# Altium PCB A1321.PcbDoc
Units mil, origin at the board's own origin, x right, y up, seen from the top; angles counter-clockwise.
Board outline 2175 x 1000 mil, 2 copper layers (Top Layer, Bottom Layer); 35 components, 22 nets, 125 pads, 412 vias.
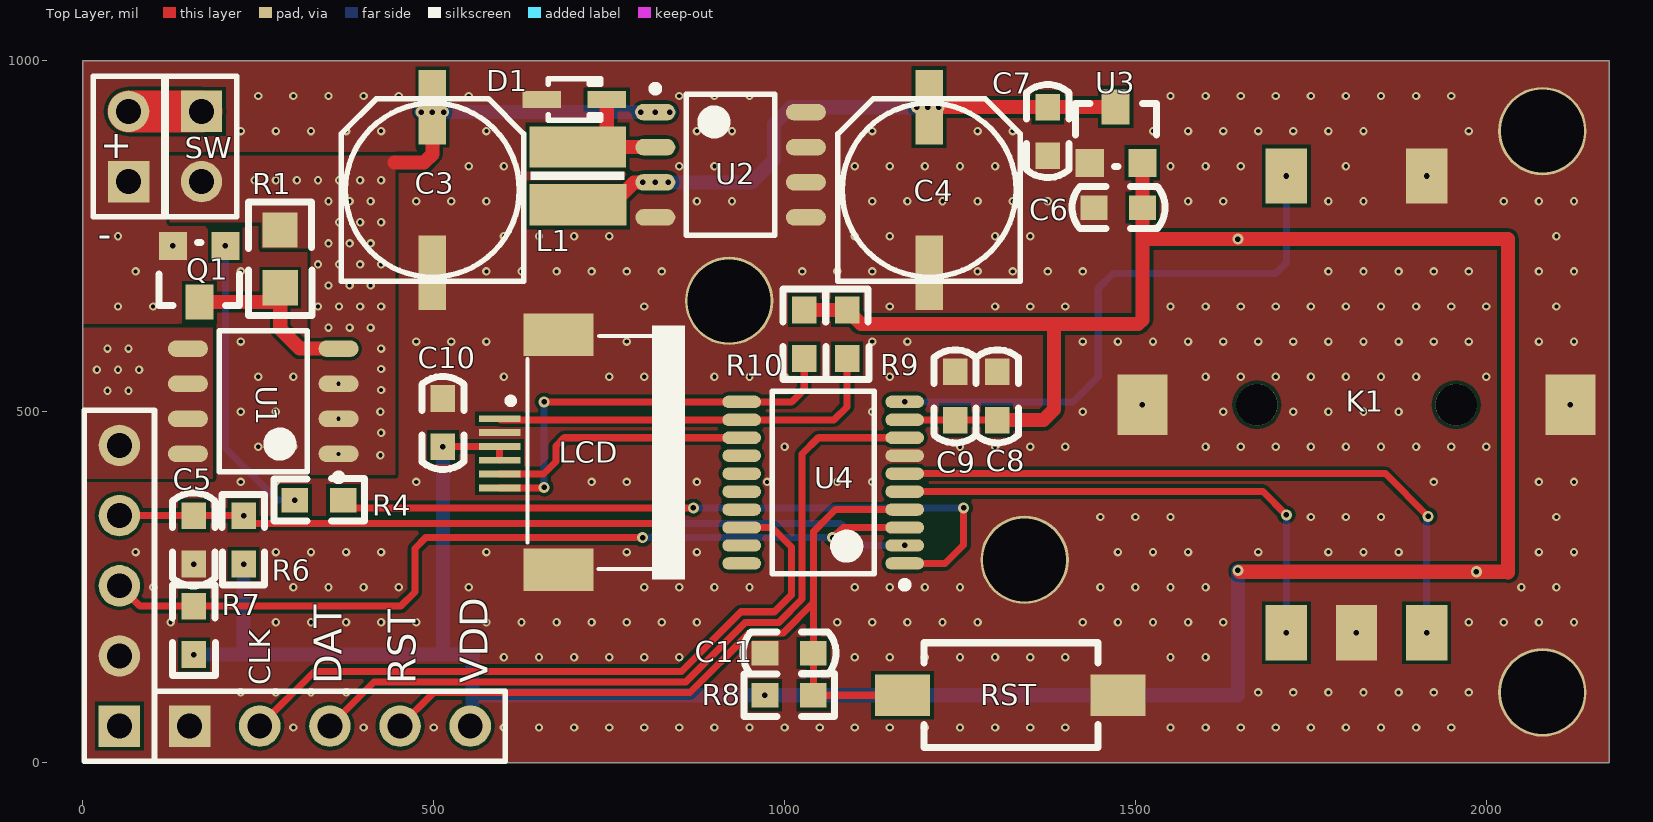
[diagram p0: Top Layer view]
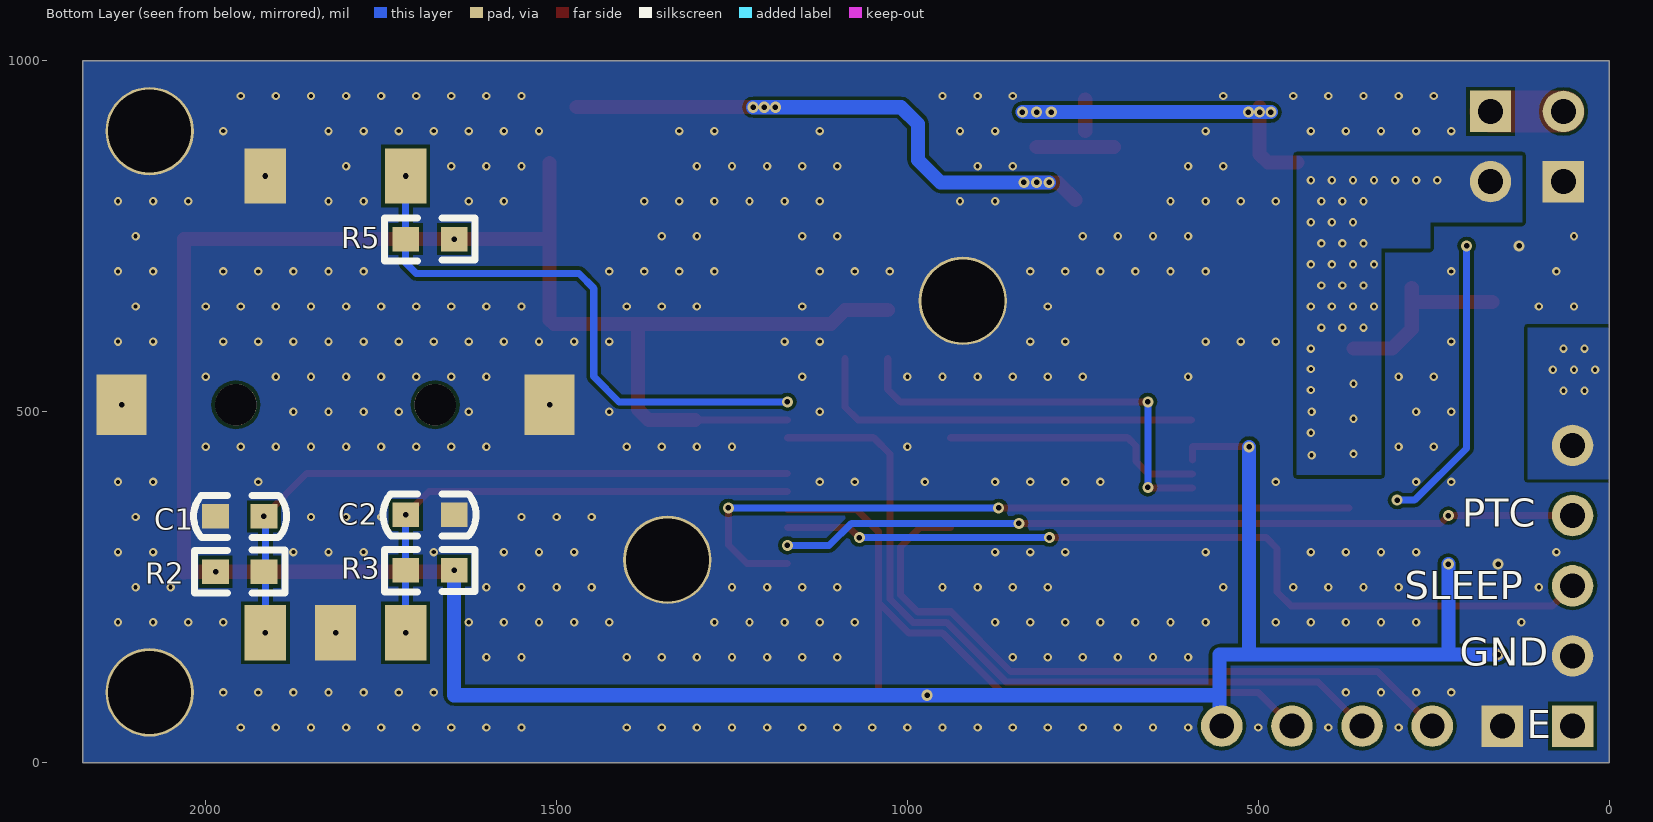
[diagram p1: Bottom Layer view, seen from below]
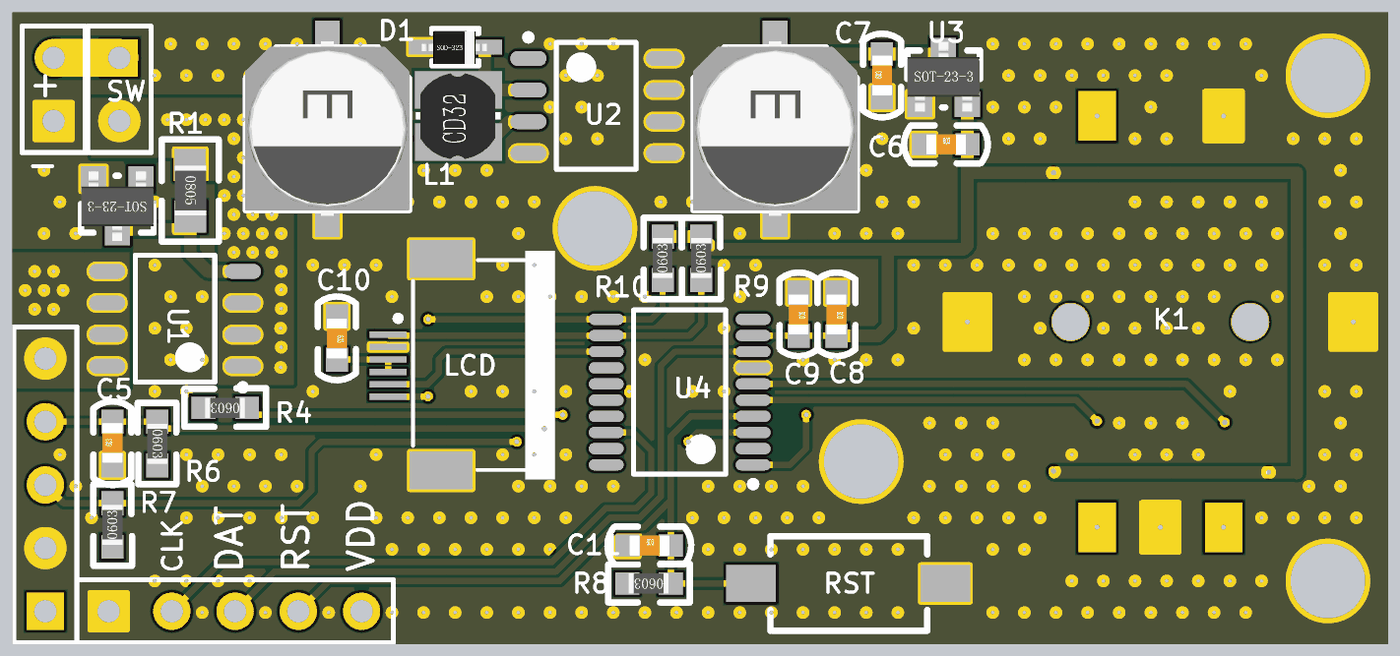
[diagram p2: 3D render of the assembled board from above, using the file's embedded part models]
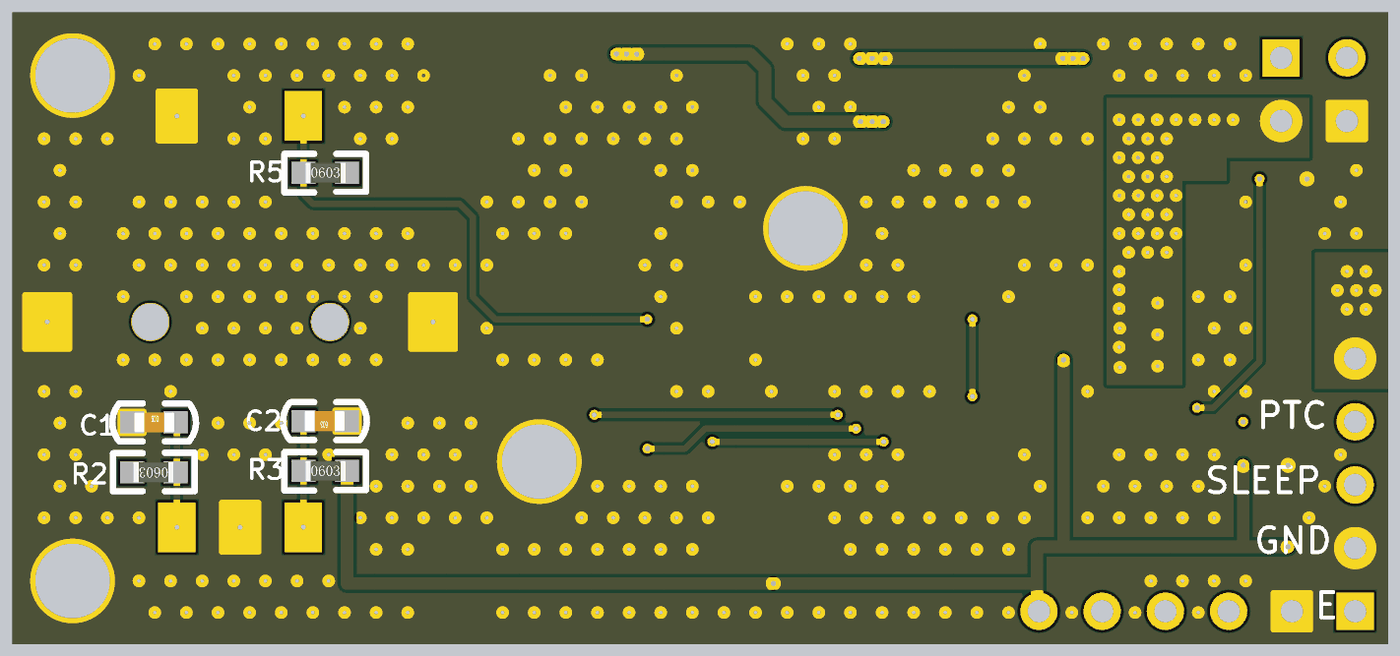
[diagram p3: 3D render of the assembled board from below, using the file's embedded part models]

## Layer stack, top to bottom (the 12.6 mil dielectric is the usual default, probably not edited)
Top Solder: solder mask 0.4, Solder Resist, Dk 3.5
Top Layer: signal copper 1.4
Dielectric 1: dielectric 12.6, FR-4, Dk 4.8
Bottom Layer: signal copper 1.4
Bottom Solder: solder mask 0.4, Solder Resist, Dk 3.5

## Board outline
0,0 0,1000 2175,1000 2175,0

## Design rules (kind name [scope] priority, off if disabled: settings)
Clearance [All] p1: gap=5
PolygonConnect [All] p1: connectstyle=Direct reliefconductorwidth=10 reliefentries=4 polygonreliefangle="90 Angle" airgapwidth=10
RoutingVias [All] p1: holewidth=8 width=14 viastyle="Through Hole" minholewidth=8 minwidth=14 maxholewidth=28 maxwidth=50
SolderMaskExpansion [All] p1: expansion=4
Width [All] p1: maxlimit=100 minlimit=5 preferedwidth=5
30 further rules are at their usual default settings.

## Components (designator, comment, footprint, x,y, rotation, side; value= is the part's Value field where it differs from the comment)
C1 "C0603" C0603 1986,351 r180 bottom
C2 "C0603" C0603 1646,353 r0 bottom
C3 "Capacitor" C6.3*6.3 498,816 r270 top
C4 "Capacitor" C6.3*6.3 1206,816 r270 top
C5 "C0603" C0603 158,283 r90 top
C6 "C0603" C0603 1441,791 r0 top
C7 "C0603" C0603 1375,865 r90 top
C8 "C0603" C0603 1303,557 r270 top
C9 "C0603" C0603 1243,557 r270 top
C10 "C0603" C0603 513,519 r270 top
C11 "C0603" C0603 972,156 r0 top
CLK "" HDR1X5 152,52 r0 top (schematic designator P4)
D1 "1N5819" SOD323 654,945 r0 top
K1 "EC12" EC12 1815,510 r0 top
L1 "CD32" CD32 705,836 r90 top
LCD "FPC6PIN-0.5" FPC6PIN-0.5 594,490 r270 top (schematic designator LCD1)
P2 "" HDR1X2 65,828 r90 top
P3 "" HDR1X5 52,52 r90 top
Q1 "S8050" SOT23 166,702 r180 top
R1 "R0805" R0805 281,759 r270 top
R2 "R0603" R0603 1917,272 r0 bottom
R3 "R0603" R0603 1715,274 r180 bottom
R4 "R0603" R0603 371,374 r180 top
R5 "R0603" R0603 1715,746 r180 bottom
R6 "R0603" R0603 229,352 r270 top
R7 "R0603" R0603 158,154 r90 top
R8 "R0603" R0603 1041,96 r180 top
R9 "R0603" R0603 1089,576 r90 top
R10 "R0603" R0603 1028,576 r90 top
RST "KEY" KEY_SMD 1475,96 r180 top (schematic designator KEY1)
SW "" HDR1X2 169,928 r270 top (schematic designator P1)
U1 "AO4407" SOP8 257,515 r180 top
U2 "XL1509" SOP8 923,852 r0 top
U3 "XC6206P332MR" SOT23 1472,889 r0 top
U4 "N76E003AT20" N76E003AT20 1055,399 r180 top

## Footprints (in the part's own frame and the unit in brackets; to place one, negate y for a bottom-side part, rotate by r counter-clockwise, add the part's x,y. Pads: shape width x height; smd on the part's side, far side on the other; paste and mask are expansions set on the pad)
C6.3*6.3 [mm]
  rect 2.7x1 smd: 1(-3,0) 2(3,0)
  silkscreen extent -3.3,-3.3 3.3,3.3, body extent -3.5,-3.3 3.5,3.3, height 5.2
C0603 [mil]
  rect 38x35 smd: 1(0,0) 2(69,0)
  silkscreen extent -31,-30 101,30, body extent 4,-16 67,16, height 12
CD32 [mm]
  rect 1.5x3.5 smd mask+0: 1(-1.047,-0.012) 2(1.05,0)
  silkscreen extent -0.14,-1.69 0.16,1.71, body extent -1.74,-1.47 1.72,1.53, height 2
EC12 [mm]
  round 1.5 hole 1.5: 0(-3.607,0) 0(3.607,0)
  rect 1.5x2 all layers, no hole: 1(2.54,-8.255) 2(0,-8.255) 3(-2.54,-8.255) 4(-2.54,8.28) 5(2.54,8.28)
  rect 1.8x2.2 all layers, no hole: 6(-7.747,0) 7(7.747,0)
FPC6PIN-0.5 [mm]
  rect 0.25x1.5 smd: 1(0,0) 2(0.5,0) 3(1,0) 4(1.5,0) 5(2,0) 6(2.5,0)
  rect 1.524x2.54 smd: 7(5.466,2.13) 8(-3.043,2.13)
  silkscreen extent -3.37,0.3 5.82,6.7, body extent -3.35,-0.15 5.8,6.5, height 2.12
HDR1X2 [mm] "Connector; Header; 2 Position"
  rect 1.5x1.5 hole 0.9: 1(0,0)
  round 1.5 hole 0.9: 2(2.54,0)
  silkscreen extent -1.27,-1.27 3.81,1.27
HDR1X5 [mm] "Connector; Header; 5 Position"
  rect 1.5x1.5 hole 0.9: 1(0,0)
  round 1.5 hole 0.9: 2(2.54,0) 3(5.08,0) 4(7.62,0) 5(10.16,0)
  silkscreen extent -1.27,-1.27 11.43,1.27
KEY_SMD [mm]
  rect 2x1.5 smd: 1(0,0) 2(7.8,0)
  silkscreen extent 0.73,-1.9 7.03,1.9, body extent -0.06,-1.94 7.83,1.91, height 2.5
N76E003AT20 [mm]
  oval 1.4x0.45 smd: 1(-2.95,2.925) 2(-2.95,2.275) 3(-2.95,1.625) 4(-2.95,0.975) 5(-2.95,0.325) 6(-2.95,-0.325) 7(-2.95,-0.975) 8(-2.95,-1.625) 9(-2.95,-2.275) 10(-2.95,-2.925) 11(2.95,-2.925) 12(2.95,-2.275) 13(2.95,-1.625) 14(2.95,-0.975) 15(2.95,-0.325) 16(2.95,0.325) 17(2.95,0.975) 18(2.95,1.625) 19(2.95,2.275) 20(2.95,2.925)
  silkscreen extent -3.08,-3.3 1.85,3.82, body extent -2.25,-3.3 2.25,3.3, height 1.2
R0603 [mil]
  rect 38x35 smd: 1(0,0) 2(69,0)
  silkscreen extent -30,-31 99,30, body extent 4,-16 66,16, height 18
R0805 [mil]
  rect 50x50 smd: 1(0,0) 2(82.3,0.2)
  silkscreen extent -40,-45 122,45, body extent 1,-24 80,25, height 22
SOD323 [mm]
  rect 1.4x0.6 smd: 1(0,0) 2(2.35,0)
  silkscreen extent 0.22,-0.75 2.12,0.75, body extent -0.17,-0.67 2.43,0.63, height 1
SOP8 [mm] "SOP, 8-Leads, Body 4.90x3.90mm, Pitch 1.27mm, IPC Medium Density"
  oval 1.45x0.6 smd: 1(-2.725,1.905) 2(-2.725,0.635) 3(-2.725,-0.635) 4(-2.725,-1.905) 5(2.725,-1.905) 6(2.725,-0.635) 7(2.725,0.635) 8(2.725,1.905)
  silkscreen extent -2.85,-2.55 1.6,2.88, body extent -2,-2.55 2,2.55, height 1.75
SOT23 [mil]
  rect 40x40 smd: 1(-37.12,-34.37) 2(37.88,-34.37)
  rect 40x50 smd: 3(-0.12,45.63)
  silkscreen extent -57,-39 58,51, body extent -57,-46 57,64, height 47

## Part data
C3 C4: library part C6.3*6.3
CLK P3: library part "Header 5", "Header, 5-Pin"
D1: library part 1N5825
P2 SW: library part "Header 2", "Header, 2-Pin"

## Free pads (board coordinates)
  round 125.98 hole 118.11: 0(2080,900) 1(2080,100) 2(921,658) 3(1342,289)

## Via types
v1: diameter 12, hole 6, Top Layer to Bottom Layer, 370 vias
v2: diameter 15.75, hole 7.87, Top Layer to Bottom Layer, 42 vias

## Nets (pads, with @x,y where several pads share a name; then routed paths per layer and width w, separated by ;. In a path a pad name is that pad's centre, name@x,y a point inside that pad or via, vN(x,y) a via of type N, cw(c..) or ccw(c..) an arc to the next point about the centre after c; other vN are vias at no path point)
DVDD_3.3: C6.2 C8.2 C9.2 C10.2 CLK.5 LCD.3 LCD.4 R2.2 R3.2 R5.2 R6.2 R7.1 R8.2 R9.2 R10.2 U3.2 U4.9 | length 4722.4
  Top Layer w10: C10.2@514.63,450.63 LCD.3 LCD.4 ; U4.9 C8.2@1302.43,488.57
  Top Layer w20: R10.2 R9.2 1109,625 1384,625 ; C8.2 1369,488 1384,503 1384,625 ; U3.2 1509.88,631 1503.88,625 1384,625 ; 1510.88,746 v2(1646,746) 2031,746 2031,271 2030,272 v2(1986,272) v2@1648,272
  Bottom Layer w20: v2(158,154) 555,154 555,96 ; 229,155 v2(229,283) ; 513,155 v2(513,450) ; CLK.5@555,55 555,96 ; v2(1646,274) 1646,96 v2(972,96) 555,96
EARTH: P3.1
GND: C1.1 C2.1 C3.2 C4.2 C5.1 C6.1 C7.1 C8.1 C9.1 C10.1 C11.1 CLK.1 D1.1 K1.2 K1.5 K1.6 K1.7 LCD.2 LCD.7 LCD.8 P2.1 P3.2 pad.0 pad.1 pad.2 pad.3 Q1.2 RST.1 U2.4 U2.5 U2.6 U2.7 U2.8 U3.1 U4.7
  other v1: 300,50 400,50 500,50 600,50 650,50 700,50 750,50 800,50 850,50 900,50 950,50 1000,50 1050,50 1100,50 1150,50 1200,50 1250,50 1300,50 1350,50 1400,50 1550,50 1600,50 1650,50 1700,50 1750,50 1800,50 1850,50 1900,50 1950,50 225,100 275,100 325,100 375,100 1675,100 1725,100 1775,100 1825,100 1875,100 1925,100 1975,100 600,150 650,150 700,150 750,150 800,150 850,150 1100,150 1150,150 1200,150 1250,150 1300,150 1350,150 1400,150 1550,150 1600,150 125,200 275,200 325,200 375,200 425,200 475,200 575,200 625,200 675,200 725,200 775,200 825,200 875,200 1075,200 1125,200 1175,200 1225,200 1275,200 1425,200 1475,200 1525,200 1575,200 1625,200 1975,200 2025,200 2075,200 2125,200 100,250 300,250 350,250 400,250 450,250 550,250 800,250 850,250 900,250 950,250 1100,250 1150,250 1200,250 1250,250 1450,250 1500,250 1550,250 1600,250 2050,250 2100,250 75,300 275,300 325,300 375,300 425,300 575,300 775,300 825,300 875,300 1475,300 1525,300 1575,300 1675,300 1775,300 1825,300 1875,300 2075,300 2125,300 1450,350 1500,350 1550,350 1750,350 1800,350 1850,350 2100,350 225,400 275,400 475,400 725,400 775,400 825,400 875,400 975,400 1075,400 1125,400 1925,400 2075,400 2125,400 250,450 300,450 1000,450 1250,450 1300,450 1350,450 1400,450 1600,450 1650,450 1700,450 1750,450 1800,450 1850,450 1900,450 1950,450 2000,450 225,500 275,500 1125,500 1425,500 1625,500 1725,500 1775,500 1825,500 1875,500 250,550 300,550 600,550 750,550 800,550 850,550 900,550 950,550 1000,550 1150,550 1600,550 1650,550 1700,550 1750,550 1800,550 1850,550 1900,550 2000,550 225,600 475,600 525,600 575,600 775,600 825,600 1125,600 1175,600 1425,600 1475,600 1525,600 1575,600 1625,600 1675,600 1725,600 1775,600 1825,600 1875,600 1925,600 1975,600 2075,600 2125,600 50,650 100,650 800,650 1150,650 1300,650 1350,650 1400,650 1550,650 1600,650 1650,650 1700,650 1750,650 1800,650 1850,650 1900,650 1950,650 2000,650 2100,650 75,700 225,700 575,700 625,700 675,700 725,700 775,700 825,700 1025,700 1075,700 1125,700 1275,700 1325,700 1375,700 1425,700 1775,700 1825,700 1875,700 1925,700 1975,700 2075,700 2125,700 50,750 600,750 650,750 700,750 750,750 1100,750 1150,750 1300,750 1350,750 2100,750 475,800 525,800 575,800 625,800 875,800 925,800 1125,800 1175,800 1225,800 1275,800 1325,800 1375,800 1575,800 1625,800 1775,800 1825,800 2025,800 2075,800 2125,800 550,850 600,850 850,850 900,850 1100,850 1150,850 1200,850 1250,850 1300,850 1550,850 1600,850 1650,850 1800,850 225,900 275,900 325,900 375,900 425,900 575,900 875,900 925,900 1125,900 1275,900 1325,900 1525,900 1575,900 1625,900 1675,900 1725,900 1775,900 1825,900 1975,900 250,950 300,950 350,950 400,950 450,950 550,950 850,950 900,950 950,950 1550,950 1600,950 1650,950 1700,950 1750,950 1800,950 1850,950 1900,950 1950,950
  other v2: 1815,185 158,283 1510,510 2120,510 128.12,736.37 1915,836
KEY_A: C2.2 K1.3 R3.1 U4.5 | length 725.6
  Top Layer w10: U4.5 1681.8,386.2 v2(1715,353)
  Bottom Layer w10: v2(1715,185) R3.1 v2(1715,353)
KEY_B: C1.2 K1.1 R2.1 U4.6 | length 935
  Top Layer w10: U4.6 1856.2,411.8 v2(1917,351)
  Bottom Layer w10: v2(1915,185) C1.2@1915,349
KEY_C: K1.4 R5.1 U4.10 | length 823.6
  Bottom Layer w10: v2(1171.14,514.16) 1411.16,514.16 1447,550 1447,676 1468,697 1700,697 1715,712 R5.1 v2(1715,836)
LCD_RST: LCD.5 U4.13 | length 379.2
  Top Layer w10: LCD.5 656.26,411.26 674,429 674,451 685.98,462.98 U4.13
NetD1_2: D1.2 L1.2 U2.2 | length 155.4
  Top Layer w20: L1.2@705.34,877 U2.2 ; L1.2@746.52,900 D1.2
NetP1_1: P2.2 SW.1 | length 104
  Top Layer w60: P2.2 SW.1
NetP3_5: P3.5 U1.5 U1.6 U1.7 U1.8
  other v1: 35,530 65,530 20,560 50,560 80,560 35,590 65,590
NetQ1_1: Q1.1 R4.2 | length 418
  Bottom Layer w10: v2(203.12,736.37) 203.12,447.88 277,374 v2(302,374)
NetQ1_3: Q1.3 R1.2 U1.4 | length 268.6
  Top Layer w20: Q1.3 R1.2@281.2,656.37 ; R1.2 281.2,617.8 309,590 U1.4
PTC: C5.2 P3.4 R6.1 U4.2 | length 1136.8
  Top Layer w10: P3.4 C5.2 v2(229,352) 240,341 v2(841,341)
  Bottom Layer w10: v2(841,341) 1080,341 1111.57,309.43 v2(1171.14,309.43)
PWM: R4.1 U4.1 | length 1031.7
  Top Layer w10: R4.1@371,363 v2(870,363) ; U4.1 1228.84,283.84 1255,310 v2(1255,363)
  Bottom Layer w10: v2(870,363) v2(1255,363)
SCL: LCD.1 R9.1 U4.12 | length 570.2
  Top Layer w10: LCD.1@595.43,488.57 U4.12 1070.57,488.57 1089,507 R9.1
SDA: LCD.6 R10.1 U4.11 | length 606.8
  Top Layer w10: LCD.6 v2@656.57,391.57 ; v2(657.16,514.16) U4.11 1010.16,514.16 1028,532 R10.1
  Bottom Layer w10: v2(657.16,392.16) v2(657.16,514.16)
SLEEP: P3.3 R7.2 U4.3 | length 1213.9
  Top Layer w10: P3.3 81,223 R7.2 453,223 473,243 473,305 488.5,320.5 v2(797.5,320.5) ; v2(1068.5,320.5) 1083.02,335.02 U4.3
  Bottom Layer w10: v2(797.5,320.5) v2(1068.5,320.5)
TICECLK: CLK.2 U4.18 | length 986.1
  Top Layer w10: CLK.2 330,130 852.93,130 937.93,215 985.79,215 1010,239.21 1010,307 981.98,335.02 U4.18
TICEDAT: CLK.3 U4.8 | length 1110.6
  Top Layer w10: CLK.3 415,115 859.14,115 944.14,200 992,200 1025,233 1025,440 1047.98,462.98 U4.8
TICERST: C11.2 CLK.4 R8.1 RST.2 U4.4 | length 1163.8
  Top Layer w10: CLK.4 500,100 865.36,100 950.36,185 998.21,185 1040,226.79 1040,227 ; RST.2 R8.1 C11.2 1041,329 1072.61,360.61 U4.4
VCC_5.0: C4.1 C7.2 L1.1 U2.3 U3.3 | length 827.7
  Top Layer w20: L1.1@760.12,801.62 785.5,827 v2(798,827) v2(815.72,827) ; C4.1 U3.3@1471.36,934.11
  Bottom Layer w20: v2(798,827) v2(815.72,827) v2(834,827) 953,827 985,859 985,910 1009,934 v2(1188,934) v2(1204,934) v2(1220,934)
VCC_IN: C3.1 R1.1 SW.2 U1.1 U1.2 U1.3 U2.1 | length 480.1
  Top Layer w20: 444,855 486,855 498,867 C3.1
  Bottom Layer w20: v2(482,927) v2(795,927) v2(815.72,927) v2(836,927)
  other v1: 424,438 364.28,440 425,470 364.28,490 424,500 425,531 364.28,540 425,561 425,590 350,620 380,620 410,620 335,650 365,650 395,650 425,650 350,680 380,680 410,680 335,710 365,710 395,710 425,710 350,740 380,740 410,740 365,770 395,770 425,770 350,800 380,800 410,800 245,830 275,830 305,830 335,830 365,830 395,830 425,830
  other v2: 498,927 514,927
pads on no net: K1.0 U4.14 U4.15 U4.16 U4.17 U4.19 U4.20

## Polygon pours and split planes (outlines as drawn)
GND on Top Layer "Top Layer-GND" (solid, remove dead copper, pour order 10): 0,1000 2175,1000 2175,0 0,0
VCC_IN on Top Layer "Top Layer-GND" (solid, remove dead copper, pour order 4): 124,865 124,770 255,770 255,733 325,733 325,410 445,410 445,865
NetP3_5 on Top Layer "Top Layer-GND" (solid, remove dead copper, pour order 2): 0,620 185,620 185,404.76 0.24,404.76 0,405
GND on Bottom Layer "Top Layer-GND" (solid, remove dead copper, pour order 12): 0,1000 2175,1000 2175,0 0,0
NetP3_5 on Bottom Layer "Top Layer-GND" (solid, remove dead copper, pour order 8): 116,620 116,404 0,404 0,463 0,620
VCC_IN on Bottom Layer "Top Layer-GND" (solid, remove dead copper, pour order 6): 124,865 124,770 255,770 255,733 325,733 325,410 445,410 445,865

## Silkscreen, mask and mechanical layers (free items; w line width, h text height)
Top Overlay:
  text "+" at 25,861 h40
  text "-" at 21,734 h40
  text "VDD" at 577,113 h40 r90
  text "DAT" at 369,112 h40 r90
  text "RST" at 474,112 h40 r90
Bottom Overlay:
  text "PTC" at 209,336 h40
  text "SLEEP" at 291,233 h40
  text "GND" at 213,138 h40
  text "E" at 117,35 h40
Top Solder:
  lines w60: 65,928 169,928
Mechanical 1:
  the board outline again, w5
